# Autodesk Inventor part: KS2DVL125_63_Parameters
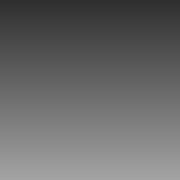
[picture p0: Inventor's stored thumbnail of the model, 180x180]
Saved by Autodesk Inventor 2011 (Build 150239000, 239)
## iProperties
Created: 2010-11
Document SubType Name: Modeling
Designer: TB
Density: 1 g/cm^3
Slaglengde: 100,000 mm
Vinkel_Minusport: 0.00 deg
Forlengelse_rør: 0.000 mm
Minusport2: 180.00 deg
Author: TB
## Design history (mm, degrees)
other parameters: "Slaglengde" = 100 [user parameter], "Forlengelse_rør" = 0 [user parameter], "Vinkel_Minusport" = 0 deg [user parameter], "Minusport2" = 180 deg [user parameter]
